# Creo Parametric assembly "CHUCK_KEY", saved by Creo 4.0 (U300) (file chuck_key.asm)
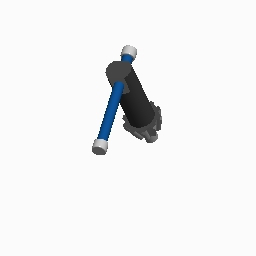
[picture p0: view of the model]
Units: millimeter Newton Second (mmNs); MM, TONNE, SECS

Created from: MMNS_ASM_DESIGN.ASM

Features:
  1. datum plane "ASM_RIGHT"
  2. datum plane "ASM_TOP"
  3. datum plane "ASM_FRONT"
  4. coordinate system
  5. component "KEY_BASE"
  6. component "KEY_HANDLE"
